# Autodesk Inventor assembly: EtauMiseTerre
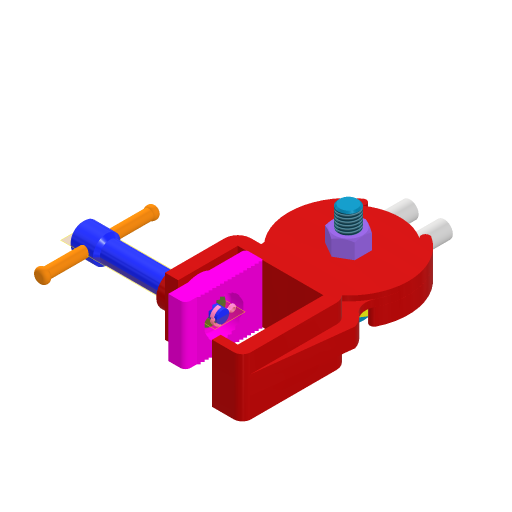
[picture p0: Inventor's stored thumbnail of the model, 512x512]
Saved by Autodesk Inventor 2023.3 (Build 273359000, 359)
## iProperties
Created: 2025-01
Part Number: EtauMiseTerre
Document SubType Name: Assembly
Designer: Thier
Author: Thier
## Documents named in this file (11)
- E:\Etau dif Model\etau mobile\Etau Mise a la terre\SolidWorks\EtauMiseTerre.iam
- E:\Etau dif Model\etau mobile\Etau Mise a la terre\SolidWorks\ecrou.ipt
- E:\Etau dif Model\etau mobile\Etau Mise a la terre\SolidWorks\etrier.ipt
- E:\Etau dif Model\etau mobile\Etau Mise a la terre\SolidWorks\goupille2.ipt
- E:\Etau dif Model\etau mobile\Etau Mise a la terre\SolidWorks\levier.ipt
- E:\Etau dif Model\etau mobile\Etau Mise a la terre\SolidWorks\rondelle.ipt
- E:\Etau dif Model\etau mobile\Etau Mise a la terre\SolidWorks\sabot.ipt
- E:\Etau dif Model\etau mobile\Etau Mise a la terre\SolidWorks\serre-tresse1.ipt
- E:\Etau dif Model\etau mobile\Etau Mise a la terre\SolidWorks\tresse.ipt
- E:\Etau dif Model\etau mobile\Etau Mise a la terre\SolidWorks\vis1.ipt
- E:\Etau dif Model\etau mobile\Etau Mise a la terre\SolidWorks\vis7.ipt
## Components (10 placed, 10 different names)
1. ecrou:1 — Logement:1, Angle:1, Angle:3
2. etrier:1 — Logement:1, Angle:1, Placage:1, Angle:2, Placage:2, Tangente:3, Logement:5, Angle:5, Angle:6
3. goupille2:1 — Placage:5, Angle:4, Placage:6
4. levier:1 — Placage:3, Placage:4
5. rondelle:1 — Logement:4
6. sabot:1 — Logement:3, Logement:4, Angle:5
7. serre-tresse1:1 — Placage:2, Tangente:2, Logement:2
8. tresse:1 — Placage:1, Angle:2, Tangente:2, Tangente:3
9. vis1:1 — Logement:2, Angle:3
10. vis7:1
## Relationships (19: Angle 6, Mate 6, Insert 5, Tangent 2)
- Logement:1 [Insert]: ecrou:1 ↔ etrier:1
- Angle:1: ecrou:1 ↔ etrier:1
- Placage:1 [Mate]: etrier:1 ↔ tresse:1
- Angle:2: etrier:1 ↔ tresse:1
- Placage:2 [Mate]: etrier:1 ↔ serre-tresse1:1
- Tangente:2: serre-tresse1:1 ↔ tresse:1
- Tangente:3: etrier:1 ↔ tresse:1
- Logement:2 [Insert]: serre-tresse1:1 ↔ vis1:1
- Angle:3: ecrou:1 ↔ vis1:1
- Placage:3 [Mate]: levier:1
- Placage:4 [Mate]: levier:1
- Logement:3 [Insert]: sabot:1
- Logement:4 [Insert]: rondelle:1 ↔ sabot:1
- Placage:5 [Mate]: goupille2:1
- Angle:4: goupille2:1
- Placage:6 [Mate]: goupille2:1
- Logement:5 [Insert]: etrier:1
- Angle:5: etrier:1 ↔ sabot:1
- Angle:6: etrier:1
